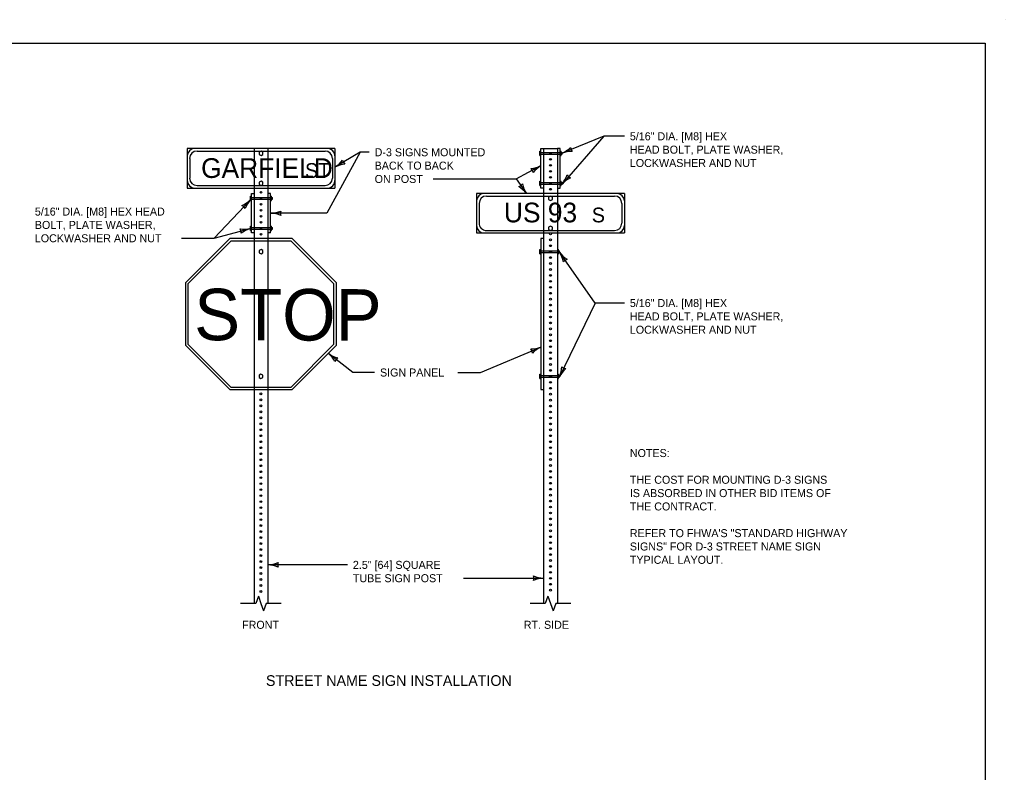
# Model space of a CAD drawing. Extents: x 49991.4 to 50021, y 49987.6 to 50011.4.
# Drawn here: x 50009.51 to 50016.9, y 49993.54 to 49999.18 of the extents above; entities that cross this region are included whole.
import ezdxf

# ---------------------------------------------------------------- set-up
doc = ezdxf.new("R2010")
doc.units = 0
for name, color, linetype in [('Level 1', 7, 'Continuous'), ('Level 2', 7, 'Continuous'), ('Level 3', 7, 'Continuous'), ('Level 4', 7, 'Continuous'), ('Level 6', 7, 'Continuous')]:
    doc.layers.add(name, color=color, linetype=linetype)

msp = doc.modelspace()

# ---------------------------------------------------------------- linework, layer by layer
at = {"layer": 'Level 1'}
for p, q in [((50016.9001, 49999.1756), (50016.9001, 49999.1756)), ((50010.7689, 49998.2099), (50010.7689, 49997.9146)), ((50011.8761, 49998.2099), (50010.7689, 49998.2099)), ((50010.8426, 49998.1914), (50011.8023, 49998.1914)), ((50011.8761, 49998.2099), (50011.8761, 49997.9146)), ((50013.4125, 49998.1579), (50013.4125, 49998.191)), ((50013.4125, 49998.191), (50013.4197, 49998.191)), ((50013.4125, 49998.1845), (50013.4197, 49998.1845)), ((50013.4125, 49998.1644), (50013.4197, 49998.1644)), ((50013.4197, 49997.9146), (50013.4197, 49998.2098)), ((50013.4197, 49998.2098), (50013.4397, 49998.2098)), ((50013.4397, 49998.2098), (50013.4397, 49997.8729)), ((50013.4397, 49998.2098), (50013.4397, 49997.9146)), ((50013.4398, 49998.2098), (50013.5439, 49998.2098)), ((50013.5438, 49998.2098), (50013.5438, 49997.8729)), ((50013.5639, 49998.2098), (50013.5439, 49998.2098)), ((50013.5439, 49998.2098), (50013.5439, 49997.9146)), ((50013.5639, 49997.9146), (50013.5639, 49998.2098)), ((50013.5639, 49998.191), (50013.5711, 49998.191)), ((50013.5639, 49998.1845), (50013.5711, 49998.1845)), ((50013.5639, 49998.1644), (50013.5711, 49998.1644)), ((50013.5711, 49998.1579), (50013.5711, 49998.191)), ((50013.5711, 49998.1811), (50013.5783, 49998.1811)), ((50013.5711, 49998.1678), (50013.5783, 49998.1678)), ((50013.5783, 49998.1678), (50013.5783, 49998.1811)), ((50010.7873, 49998.1361), (50010.7873, 49997.9884)), ((50011.8577, 49998.1361), (50011.8577, 49997.9884)), ((50013.4125, 49998.1579), (50013.4197, 49998.1579)), ((50013.5639, 49998.1579), (50013.5711, 49998.1579)), ((50013.4125, 49997.9334), (50013.4125, 49997.9665)), ((50013.4125, 49997.9665), (50013.4197, 49997.9665)), ((50013.4125, 49997.96), (50013.4197, 49997.96)), ((50013.4125, 49997.9399), (50013.4197, 49997.9399)), ((50013.5639, 49997.9665), (50013.5711, 49997.9665)), ((50013.5639, 49997.96), (50013.5711, 49997.96)), ((50013.5639, 49997.9399), (50013.5711, 49997.9399)), ((50013.5711, 49997.9334), (50013.5711, 49997.9665)), ((50013.5711, 49997.9566), (50013.5783, 49997.9566)), ((50013.5711, 49997.9433), (50013.5783, 49997.9433)), ((50013.5783, 49997.9433), (50013.5783, 49997.9566)), ((50010.7689, 49997.9146), (50011.8761, 49997.9146)), ((50010.8426, 49997.9331), (50011.8023, 49997.9331)), ((50011.25, 49997.873), (50011.27, 49997.873)), ((50011.25, 49997.5777), (50011.25, 49997.8729)), ((50011.27, 49997.9146), (50011.27, 49997.536)), ((50011.27, 49997.873), (50011.27, 49997.5777)), ((50011.3742, 49997.9146), (50011.3742, 49997.536)), ((50011.3942, 49997.873), (50011.3742, 49997.873)), ((50011.3742, 49997.873), (50011.3742, 49997.5777)), ((50011.3942, 49997.5777), (50011.3942, 49997.8729)), ((50012.938, 49997.8729), (50012.938, 49997.5777)), ((50014.0451, 49997.8729), (50012.938, 49997.8729)), ((50013.4125, 49997.9334), (50013.4197, 49997.9334)), ((50013.4397, 49997.9146), (50013.4197, 49997.9146)), ((50013.5439, 49997.9146), (50013.5639, 49997.9146)), ((50013.5639, 49997.9334), (50013.5711, 49997.9334)), ((50014.0451, 49997.8729), (50014.0451, 49997.5777)), ((50011.2428, 49997.821), (50011.2428, 49997.8541)), ((50011.2428, 49997.8541), (50011.25, 49997.8541)), ((50011.2428, 49997.8476), (50011.25, 49997.8476)), ((50011.2428, 49997.8275), (50011.25, 49997.8275)), ((50011.2428, 49997.821), (50011.25, 49997.821)), ((50011.3942, 49997.8541), (50011.4014, 49997.8541)), ((50011.3942, 49997.8476), (50011.4014, 49997.8476)), ((50011.3942, 49997.8275), (50011.4014, 49997.8275)), ((50011.3942, 49997.821), (50011.4014, 49997.821)), ((50011.4014, 49997.821), (50011.4014, 49997.8541)), ((50011.4014, 49997.8442), (50011.4086, 49997.8442)), ((50011.4014, 49997.8309), (50011.4086, 49997.8309)), ((50011.4086, 49997.8309), (50011.4086, 49997.8442)), ((50012.9565, 49997.7992), (50012.9565, 49997.6515)), ((50013.0118, 49997.8545), (50013.9713, 49997.8545)), ((50014.0267, 49997.7992), (50014.0267, 49997.6515)), ((50011.2428, 49997.5965), (50011.2428, 49997.6296)), ((50011.2428, 49997.6296), (50011.25, 49997.6296)), ((50011.2428, 49997.6231), (50011.25, 49997.6231)), ((50011.2428, 49997.603), (50011.25, 49997.603)), ((50011.2428, 49997.5965), (50011.25, 49997.5965)), ((50011.27, 49997.5777), (50011.25, 49997.5777)), ((50011.3942, 49997.5777), (50011.3742, 49997.5777)), ((50011.3942, 49997.6296), (50011.4014, 49997.6296)), ((50011.3942, 49997.6231), (50011.4014, 49997.6231)), ((50011.3942, 49997.603), (50011.4014, 49997.603)), ((50011.3942, 49997.5965), (50011.4014, 49997.5965)), ((50011.4014, 49997.5965), (50011.4014, 49997.6296)), ((50011.4014, 49997.6197), (50011.4086, 49997.6197)), ((50011.4014, 49997.6064), (50011.4086, 49997.6064)), ((50011.4086, 49997.6064), (50011.4086, 49997.6197)), ((50012.938, 49997.5777), (50014.0451, 49997.5777)), ((50013.0118, 49997.5961), (50013.9713, 49997.5961)), ((50013.4395, 49997.5777), (50013.4395, 49994.8019)), ((50013.5437, 49997.5777), (50013.5437, 49994.8019)), ((50013.4196, 49997.536), (50013.4196, 49996.4044)), ((50013.4395, 49997.536), (50013.4196, 49997.536)), ((50013.4124, 49997.421), (50013.4124, 49997.4541)), ((50013.4124, 49997.4541), (50013.4196, 49997.4541)), ((50013.4124, 49997.4476), (50013.4196, 49997.4476)), ((50013.4124, 49997.4275), (50013.4196, 49997.4275)), ((50013.5437, 49997.4541), (50013.5509, 49997.4541)), ((50013.5437, 49997.4476), (50013.5509, 49997.4476)), ((50013.5437, 49997.4275), (50013.5509, 49997.4275)), ((50013.5509, 49997.421), (50013.5509, 49997.4541)), ((50013.5509, 49997.4442), (50013.5581, 49997.4442)), ((50013.5509, 49997.4309), (50013.5581, 49997.4309)), ((50013.5581, 49997.4309), (50013.5581, 49997.4442)), ((50013.4124, 49997.421), (50013.4196, 49997.421)), ((50013.5437, 49997.421), (50013.5509, 49997.421)), ((50013.4124, 49996.4864), (50013.4124, 49996.5195)), ((50013.4124, 49996.5195), (50013.4196, 49996.5195)), ((50013.4124, 49996.513), (50013.4196, 49996.513)), ((50013.4124, 49996.4929), (50013.4196, 49996.4929)), ((50013.4124, 49996.4864), (50013.4196, 49996.4864)), ((50013.5437, 49996.5195), (50013.5509, 49996.5195)), ((50013.5437, 49996.513), (50013.5509, 49996.513)), ((50013.5437, 49996.4929), (50013.5509, 49996.4929)), ((50013.5437, 49996.4864), (50013.5509, 49996.4864)), ((50013.5509, 49996.4864), (50013.5509, 49996.5195)), ((50013.5509, 49996.5096), (50013.5581, 49996.5096)), ((50013.5509, 49996.4963), (50013.5581, 49996.4963)), ((50013.5581, 49996.4963), (50013.5581, 49996.5096)), ((50011.2694, 49996.4044), (50011.2694, 49994.8019)), ((50011.3736, 49996.4044), (50011.3736, 49994.8019)), ((50013.4196, 49996.4044), (50013.4395, 49996.4044))]:
    msp.add_line(p, q, dxfattribs=at)
for points in [[(49999.3835, 49998.9992), (50016.7501, 49998.9992), (50016.7501, 49987.7988), (49999.3835, 49987.7988)], [(50011.3079, 49998.1826), (50011.3079, 49998.1661), (50011.3222, 49998.1578), (50011.3365, 49998.1661), (50011.3365, 49998.1826), (50011.3222, 49998.1909)], [(50011.3078, 49997.958), (50011.3078, 49997.9415), (50011.3221, 49997.9332), (50011.3364, 49997.9415), (50011.3364, 49997.958), (50011.3221, 49997.9663)], [(50013.4775, 49997.8458), (50013.4775, 49997.8293), (50013.4918, 49997.821), (50013.5061, 49997.8293), (50013.5061, 49997.8458), (50013.4918, 49997.8541)], [(50013.4773, 49997.6213), (50013.4773, 49997.6048), (50013.4916, 49997.5965), (50013.5059, 49997.6048), (50013.5059, 49997.6213), (50013.4916, 49997.6296)], [(50011.8873, 49996.7358), (50011.8873, 49997.2046), (50011.5559, 49997.536), (50011.0871, 49997.536), (50010.7557, 49997.2046), (50010.7557, 49996.7358), (50011.0871, 49996.4044), (50011.5559, 49996.4044)], [(50011.8684, 49996.7436), (50011.8684, 49997.1968), (50011.5481, 49997.5171), (50011.0949, 49997.5171), (50010.7746, 49997.1968), (50010.7746, 49996.7436), (50011.0949, 49996.4233), (50011.5481, 49996.4233)], [(50011.3076, 49997.4458), (50011.3076, 49997.4293), (50011.3219, 49997.421), (50011.3362, 49997.4293), (50011.3362, 49997.4458), (50011.3219, 49997.4541)], [(50011.3072, 49996.5112), (50011.3072, 49996.4947), (50011.3215, 49996.4864), (50011.3358, 49996.4947), (50011.3358, 49996.5112), (50011.3215, 49996.5195)]]:
    msp.add_lwpolyline(points, close=True, dxfattribs=at)
for centre in [(50013.4917, 49998.1745), (50013.4917, 49998.1296), (50013.4917, 49998.0847), (50013.4917, 49998.0398), (50013.4917, 49997.9949), (50013.4917, 49997.95), (50011.322, 49997.8824), (50013.4917, 49997.9052), (50011.322, 49997.8375), (50011.322, 49997.7927), (50011.322, 49997.7478), (50011.322, 49997.7029), (50011.322, 49997.658), (50011.322, 49997.6131), (50011.322, 49997.5682), (50013.4917, 49997.571), (50013.4917, 49997.5265), (50013.4917, 49997.482), (50013.4917, 49997.4376), (50013.4917, 49997.3931), (50013.4917, 49997.3486), (50013.4917, 49997.3041), (50013.4917, 49997.2596), (50013.4917, 49997.2151), (50013.4917, 49997.1706), (50013.4917, 49997.1261), (50013.4917, 49997.0816), (50013.4917, 49997.0371), (50013.4917, 49996.9926), (50013.4917, 49996.9481), (50013.4917, 49996.9036), (50013.4917, 49996.8591), (50013.4917, 49996.8146), (50013.4917, 49996.7701), (50013.4917, 49996.7256), (50013.4917, 49996.6811), (50013.4917, 49996.6366), (50013.4917, 49996.5921), (50013.4917, 49996.5476), (50013.4917, 49996.5031), (50013.4917, 49996.4586), (50013.4917, 49996.4141), (50011.3214, 49996.3723), (50011.3214, 49996.3274), (50013.4917, 49996.3696), (50013.4917, 49996.3251), (50011.3214, 49996.2825), (50011.3214, 49996.2376), (50013.4917, 49996.2806), (50013.4917, 49996.2361), (50011.3214, 49996.1927), (50013.4917, 49996.1916), (50011.3214, 49996.1479), (50011.3214, 49996.103), (50013.4917, 49996.1471), (50013.4917, 49996.1026), (50011.3214, 49996.0581), (50011.3214, 49996.0132), (50013.4917, 49996.0581), (50013.4917, 49996.0136), (50011.3214, 49995.9683), (50013.4917, 49995.9691), (50011.3214, 49995.9235), (50011.3214, 49995.8786), (50013.4917, 49995.9246), (50013.4917, 49995.8801), (50011.3214, 49995.8337), (50013.4917, 49995.8356), (50013.4917, 49995.7911), (50011.3214, 49995.7888), (50011.3214, 49995.7439), (50013.4917, 49995.7466), (50011.3214, 49995.6991), (50011.3214, 49995.6542), (50013.4917, 49995.7021), (50013.4917, 49995.6576), (50011.3214, 49995.6093), (50013.4917, 49995.6131), (50011.3214, 49995.5644), (50011.3214, 49995.5195), (50013.4917, 49995.5686), (50013.4917, 49995.5241), (50011.3214, 49995.4747), (50011.3214, 49995.4298), (50013.4917, 49995.4796), (50013.4917, 49995.4351), (50011.3214, 49995.3849), (50013.4917, 49995.3906), (50011.3214, 49995.34), (50011.3214, 49995.2951), (50013.4917, 49995.3461), (50013.4917, 49995.3016), (50011.3214, 49995.2503), (50011.3214, 49995.2054), (50013.4917, 49995.2571), (50013.4917, 49995.2126), (50011.3214, 49995.1605), (50013.4917, 49995.1681), (50011.3214, 49995.1156), (50011.3214, 49995.0707), (50013.4917, 49995.1236), (50013.4917, 49995.0791), (50011.3214, 49995.0259), (50011.3214, 49994.981), (50013.4917, 49995.0346), (50013.4917, 49994.9901), (50011.3214, 49994.9361), (50013.4917, 49994.9456), (50011.3214, 49994.8912), (50013.4917, 49994.9011)]:
    msp.add_circle(centre, 0.00659, dxfattribs=at)
for centre, start, end in [((50010.8242, 49998.1546), 90.67268, 180), ((50010.8426, 49998.1361), 90, 180), ((50011.8023, 49998.1361), 0, 90), ((50011.8207, 49998.1546), 0, 90), ((50010.8242, 49997.97), 180, 270), ((50010.8426, 49997.9885), 180, 270), ((50011.8023, 49997.9885), 270, 0), ((50011.8207, 49997.97), 270, 0), ((50012.9933, 49997.8176), 91.82918, 180), ((50013.9898, 49997.8176), 0, 90), ((50013.0118, 49997.7992), 90, 180), ((50013.9713, 49997.7992), 0, 90), ((50013.0118, 49997.6515), 179.95698, 270), ((50013.9713, 49997.6515), 270, 0), ((50012.9933, 49997.6331), 180, 270), ((50013.9897, 49997.6331), 270, 0)]:
    msp.add_arc(centre, 0.0554, start, end, dxfattribs=at)
at = {"layer": 'Level 3'}
for p, q in [((50013.8912, 49998.3021), (50013.5783, 49998.1751)), ((50013.8912, 49998.3021), (50013.5783, 49997.9441)), ((50014.0463, 49998.3021), (50013.8912, 49998.3021)), ((50012.065, 49998.1824), (50011.8165, 49997.7253)), ((50012.065, 49998.1824), (50011.8761, 49998.0698)), ((50012.1336, 49998.1824), (50012.065, 49998.1824)), ((50013.234, 49997.9824), (50013.4197, 49998.0821)), ((50012.6128, 49997.9824), (50013.234, 49997.9824)), ((50013.234, 49997.9824), (50013.3111, 49997.8729)), ((50010.9705, 49997.5379), (50011.2428, 49997.8272)), ((50011.8165, 49997.7253), (50011.3942, 49997.7253)), ((50010.9705, 49997.5379), (50011.2428, 49997.6117)), ((50010.726, 49997.5379), (50010.9705, 49997.5379)), ((50013.8273, 49997.0527), (50013.5581, 49997.4329)), ((50013.8273, 49997.0527), (50013.5581, 49996.5001)), ((50014.0463, 49997.0527), (50013.8273, 49997.0527)), ((50012.9665, 49996.5322), (50013.4196, 49996.7228)), ((50012.0092, 49996.5322), (50011.827, 49996.6755)), ((50012.1736, 49996.5322), (50012.0092, 49996.5322)), ((50012.7976, 49996.5322), (50012.9665, 49996.5322)), ((50011.9706, 49995.0908), (50011.3736, 49995.0908)), ((50012.8398, 49994.9908), (50013.4395, 49994.9908))]:
    msp.add_line(p, q, dxfattribs=at)
for centre, radius, start, end in [((50013.4801, 49998.3864), 0.233, 294.92218, 314.17203), ((50013.6534, 49997.9658), 0.2223, 89.55088, 109.73439), ((50013.6971, 49998.2233), 0.0548, 184.23369, 219.95605), ((50011.7471, 49998.2638), 0.233, 303.62574, 322.87559), ((50011.982, 49997.8743), 0.2223, 98.25444, 118.43795), ((50011.9862, 49998.1355), 0.0548, 192.93725, 228.65961), ((50013.3227, 49998.2822), 0.2223, 275.68681, 295.87031), ((50013.3067, 49998.0215), 0.0548, 10.36961, 46.09198), ((50013.5399, 49997.8825), 0.233, 121.05811, 140.30796), ((50013.2373, 49997.9778), 0.0548, 287.28856, 323.01093), ((50013.498, 49997.9933), 0.2223, 192.60576, 212.78926), ((50013.3955, 49998.0886), 0.233, 321.67611, 340.92596), ((50013.7395, 49997.791), 0.2223, 116.30481, 136.48832), ((50013.6627, 49998.0406), 0.0548, 210.98762, 246.70998), ((50013.1274, 49997.7296), 0.233, 37.97706, 57.22691), ((50011.0873, 49997.9862), 0.2223, 294.18983, 314.37334), ((50011.4201, 49997.6761), 0.233, 139.56113, 158.81098), ((50011.1549, 49997.7339), 0.0548, 28.87264, 64.595), ((50011.3827, 49997.958), 0.233, 272.82731, 292.07716), ((50011.385, 49997.5032), 0.2223, 67.45601, 87.63952), ((50011.5224, 49997.7253), 0.0548, 162.13882, 197.86118), ((50011.1935, 49997.8285), 0.2223, 262.61546, 282.79897), ((50011.119, 49997.5782), 0.0548, 357.29827, 33.02063), ((50011.3147, 49997.3901), 0.233, 107.98676, 127.23661), ((50013.3715, 49997.312), 0.2223, 12.76001, 32.94352), ((50013.7414, 49997.5768), 0.233, 218.13131, 237.38116), ((50013.6322, 49997.3282), 0.0548, 107.44282, 143.16518), ((50013.3419, 49996.9311), 0.2223, 270.27044, 290.45395), ((50013.3014, 49996.6731), 0.0548, 4.95325, 40.67561), ((50013.5204, 49996.5128), 0.233, 115.64174, 134.89159), ((50011.6825, 49996.5066), 0.2223, 29.27102, 49.45453), ((50011.9618, 49996.8656), 0.233, 234.64232, 253.89217), ((50011.9278, 49996.5963), 0.0548, 123.95383, 159.67619), ((50013.3438, 49996.5916), 0.233, 336.85708, 356.10693), ((50013.7538, 49996.3946), 0.2223, 131.48578, 151.66929), ((50013.6142, 49996.6153), 0.0548, 226.16859, 261.89095), ((50011.3621, 49995.3235), 0.233, 272.82731, 292.07716), ((50011.3644, 49994.8687), 0.2223, 67.45601, 87.63952), ((50011.5018, 49995.0908), 0.0548, 162.13882, 197.86118), ((50013.4486, 49995.213), 0.2223, 247.45601, 267.63952), ((50013.3113, 49994.9908), 0.0548, 342.13882, 17.86118), ((50013.451, 49994.7581), 0.233, 92.82731, 112.07716)]:
    msp.add_arc(centre, radius, start, end, dxfattribs=at)
at = {"layer": 'Level 4'}
for p, q in [((50011.2701, 49998.2099), (50011.27, 49997.9146)), ((50011.3743, 49998.2097), (50011.3742, 49997.9145)), ((50013.4197, 49998.1811), (50013.5639, 49998.1811)), ((50013.4197, 49998.1678), (50013.5639, 49998.1678)), ((50013.4197, 49997.9566), (50013.5639, 49997.9566)), ((50013.4197, 49997.9433), (50013.5639, 49997.9433)), ((50013.4397, 49997.8729), (50013.4395, 49997.5777)), ((50013.5438, 49997.8729), (50013.5437, 49997.5777)), ((50011.25, 49997.8442), (50011.3942, 49997.8442)), ((50011.25, 49997.8309), (50011.3942, 49997.8309)), ((50011.25, 49997.6197), (50011.3942, 49997.6197)), ((50011.25, 49997.6064), (50011.3942, 49997.6064)), ((50011.27, 49997.536), (50011.2694, 49996.4044)), ((50011.3742, 49997.536), (50011.3736, 49996.4044)), ((50013.4196, 49997.4442), (50013.5437, 49997.4442)), ((50013.4196, 49997.4309), (50013.5437, 49997.4309)), ((50013.4196, 49996.5096), (50013.5437, 49996.5096)), ((50013.4196, 49996.4963), (50013.5437, 49996.4963))]:
    msp.add_line(p, q, dxfattribs=at)
at = {"layer": 'Level 6'}
for p, q in [((50011.3022, 49994.8567), (50011.2827, 49994.8019)), ((50011.3022, 49994.8567), (50011.3216, 49994.8019)), ((50013.4723, 49994.8567), (50013.4528, 49994.8019)), ((50013.4723, 49994.8567), (50013.4917, 49994.8019)), ((50011.2827, 49994.8019), (50011.1694, 49994.8019)), ((50011.3216, 49994.8019), (50011.341, 49994.7471)), ((50011.3605, 49994.8019), (50011.341, 49994.7471)), ((50011.4736, 49994.8019), (50011.3605, 49994.8019)), ((50013.4528, 49994.8019), (50013.3395, 49994.8019)), ((50013.4917, 49994.8019), (50013.5111, 49994.7471)), ((50013.5306, 49994.8019), (50013.5111, 49994.7471)), ((50013.6437, 49994.8019), (50013.5306, 49994.8019))]:
    msp.add_line(p, q, dxfattribs=at)

# ---------------------------------------------------------------- texts
at = {"layer": 'Level 1'}
for s, height, rotation, p in [('GARFIELD', 0.14762, 0.00007, (50010.8729, 49997.9901)), ('ST', 0.11072, 359.99903, (50011.6515, 49997.9901)), ('US 93', 0.14762, 0.00007, (50013.1425, 49997.6571)), ('S', 0.1107, 359.99903, (50013.8011, 49997.6571)), ('STOP', 0.38578, 359.83331, (50010.8207, 49996.7744))]:
    msp.add_text(s, height=height, rotation=rotation, dxfattribs=at).set_placement(p)
at = {"layer": 'Level 2'}
for s, height, p in [('5/16" DIA. [M8] HEX ', 0.06, (50014.0863, 49998.2721)), ('D-3 SIGNS MOUNTED', 0.06, (50012.1736, 49998.1524)), ('HEAD BOLT, PLATE WASHER,', 0.06, (50014.0863, 49998.1721)), ('BACK TO BACK', 0.06, (50012.1736, 49998.0524)), ('LOCKWASHER AND NUT', 0.06, (50014.0863, 49998.0721)), ('ON POST', 0.06, (50012.1736, 49997.9524)), ('5/16" DIA. [M8] HEX HEAD', 0.06, (50009.6268, 49997.7079)), ('BOLT, PLATE WASHER,', 0.06, (50009.6268, 49997.6079)), ('LOCKWASHER AND NUT', 0.06, (50009.6268, 49997.5079)), ('5/16" DIA. [M8] HEX ', 0.06, (50014.0863, 49997.0227)), ('HEAD BOLT, PLATE WASHER,', 0.06, (50014.0863, 49996.9227)), ('LOCKWASHER AND NUT', 0.06, (50014.0863, 49996.8227)), ('SIGN PANEL', 0.06, (50012.2136, 49996.5022)), ('NOTES:', 0.06, (50014.0863, 49995.8986)), ('THE COST FOR MOUNTING D-3 SIGNS', 0.06, (50014.0863, 49995.6986)), ('IS ABSORBED IN OTHER BID ITEMS OF', 0.06, (50014.0863, 49995.5986)), ('THE CONTRACT.', 0.06, (50014.0863, 49995.4986)), ('REFER TO FHWA\'S "STANDARD HIGHWAY', 0.06, (50014.0863, 49995.2986)), ('SIGNS" FOR D-3 STREET NAME SIGN', 0.06, (50014.0863, 49995.1986)), ('TYPICAL LAYOUT.', 0.06, (50014.0863, 49995.0986)), ('2.5" [64] SQUARE', 0.06, (50012.0106, 49995.0608)), ('TUBE SIGN POST', 0.06, (50012.0106, 49994.9608)), ('FRONT', 0.06, (50011.1802, 49994.6117)), ('RT. SIDE', 0.06, (50013.2914, 49994.6117)), ('STREET NAME SIGN INSTALLATION', 0.08, (50011.3591, 49994.184))]:
    msp.add_text(s, height=height, dxfattribs=at).set_placement(p)

doc.saveas('drawing.dxf')
